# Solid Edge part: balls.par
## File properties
Title: Bearing
Author: Abhinav Rai
Template: Normal.par
Last saved by: Cadcim
Revision: 8
Application: Solid Edge
Material: aluminum
Accuracy: 0.99
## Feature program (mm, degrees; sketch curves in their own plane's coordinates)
sketch for "unnamed RevolvedProtrusion 1" plane through (0, 0, 0) normal (0, -1, 0) x-axis (1, 0, 0)
  arc centre (0, 0) radius 6.604 from (0, 6.604) to (0, -6.604) cw
  line (0, 6.604) -> (0, -6.604)
revolve "unnamed RevolvedProtrusion 1" add full turn 360 deg
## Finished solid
Body 1: solid body, 1 face, 0 edges, 0 vertices.
  Faces by surface: sphere 1
Spherical faces by radius (mm): R6.604 x1
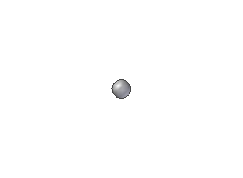
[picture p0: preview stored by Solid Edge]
